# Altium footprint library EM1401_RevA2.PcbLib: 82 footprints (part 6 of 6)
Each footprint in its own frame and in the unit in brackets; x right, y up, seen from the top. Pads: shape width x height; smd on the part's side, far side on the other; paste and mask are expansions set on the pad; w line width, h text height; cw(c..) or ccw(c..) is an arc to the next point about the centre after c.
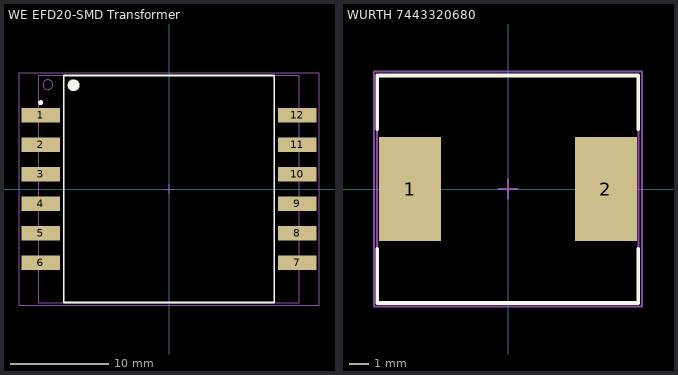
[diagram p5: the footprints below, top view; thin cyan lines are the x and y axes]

## WE EFD20-SMD Transformer [mm] "Tigon Forward Transformer"
height 11.43
pads (12):
  rect 3.9x1.45 smd: 1(-13.05,7.5) 2(-13.05,4.5) 3(-13.05,1.5) 4(-13.05,-1.5) 5(-13.05,-4.5) 6(-13.05,-7.5) 7(13.05,-7.5) 8(13.05,-4.5) 9(13.05,-1.5) 10(13.05,1.5) 11(13.05,4.5) 12(13.05,7.5)
Top Overlay:
  circle w0.25: c-13.05,8.775 r0.125
  circle w0.6: c-9.7,10.55 r0.3
  lines w0.2: -10.7,-11.55 -10.7,11.55 10.7,11.55 10.7,-11.55 -10.7,-11.55
Mechanical 5:
  text ".designator" at 0.42,-4.965 h1.02
Mechanical 13:
  circle w0.1: c-12.31,10.605 r0.5
  lines w0.1: -13.26,-11.555 -13.26,11.555 13.26,11.555 13.26,-11.555 -13.26,-11.555
Mechanical 15:
  lines w0.1: -0.5,0 0.5,0 ; 0,-0.5 0,0.5 ; -15.25,-11.8 -15.25,11.8 15.25,11.8 15.25,-11.8 -15.25,-11.8
3D body: height 11.43, standoff 0.25, extent -13.26,-11.555 13.26,11.555

## WURTH 7443320680 [mm] "Wurth Inductor 6.8uH - Power Choke WE-HCC"
height 4
pads (2):
  rect 3.2x5.4 smd: 1(-5.077,0) 2(5.077,0)
Top Overlay:
  lines w0.2: -6.782,-3.1 -6.782,-5.918 6.756,-5.918 6.756,-3.1 ; -6.782,3.1 -6.782,5.893 6.756,5.893 6.756,3.1
Mechanical 13:
  lines w0.1: -6.782,-5.85 -6.782,5.85 6.756,5.85 6.756,-5.85 -6.782,-5.85
Mechanical 15:
  lines w0.1: -0.5,0 0.5,0 ; 0,-0.5 0,0.5 ; -6.95,-6.1 6.95,-6.1 6.95,6.1 -6.95,6.1 -6.95,-6.1
3D body: height 4, standoff 0, extent -6.782,-5.85 6.68,5.85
